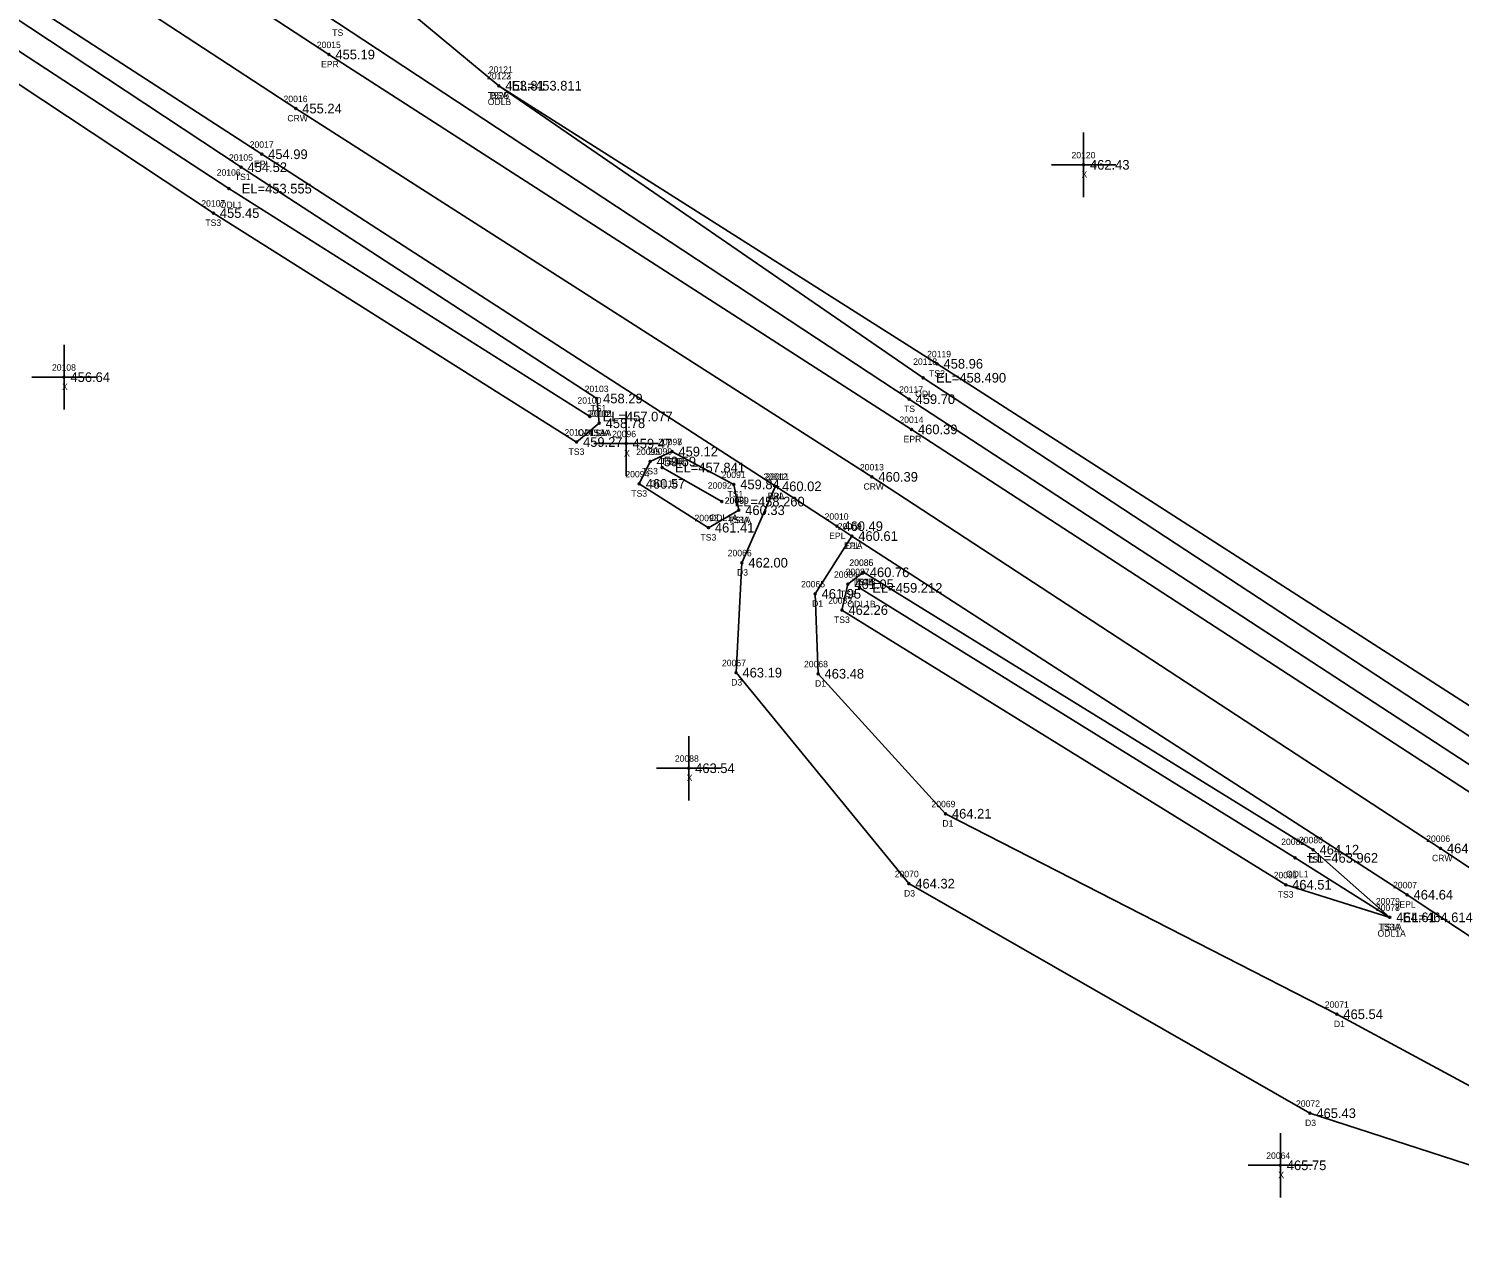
# Model space of a CAD drawing. Extents: x 1797709 to 1799052, y 896018 to 896955.
# Drawn here: x 1798706.7 to 1798928.8, y 896063.3 to 896253.9 of the extents above; entities that cross this region are included whole.
import ezdxf

# ---------------------------------------------------------------- set-up
doc = ezdxf.new("R2010")
doc.units = 0
for name, color, linetype in [('RD_DTM_BkLn1', 7, 'Continuous'), ('RD_DTM_BkLn2', 7, 'Continuous'), ('RD_DTM_BkLn_txCode', 7, 'Continuous'), ('RD_EX_Driveway', 7, 'Continuous'), ('RD_EX_Driveway_txCode', 7, 'Continuous'), ('RD_EX_H2O', 7, 'Continuous'), ('RD_EX_H2O_txCode', 7, 'Continuous'), ('RD_EX_Misc', 7, 'Continuous'), ('RD_EX_Misc_txCode', 7, 'Continuous'), ('RD_EX_Road', 7, 'Continuous'), ('RD_EX_Road_txCode', 7, 'Continuous'), ('RD_EX_TX_Driveway_ELEV', 7, 'Continuous'), ('RD_EX_TX_H2O_ELEV', 7, 'Continuous'), ('RD_EX_TX_Misc_ELEV', 7, 'Continuous'), ('RD_EX_TX_Road_ELEV', 7, 'Continuous'), ('RD_HC_Survey_ELEV', 7, 'Continuous'), ('RD_HC_Survey_txCode', 7, 'Continuous'), ('RD_SMD_Locator', 7, 'Continuous')]:
    doc.layers.add(name, color=color, linetype=linetype)

msp = doc.modelspace()

# ---------------------------------------------------------------- linework, layer by layer
at = {"layer": 'RD_DTM_BkLn1'}
msp.add_lwpolyline([(1799011.08, 896069.91), (1798925.85, 896126.62), (1798837.59, 896184.3), (1798748.15, 896241.48), (1798659.28, 896299.6), (1798569.04, 896359.56), (1798481.49, 896418.06), (1798400.67, 896472.53)], dxfattribs=at)
at = {"layer": 'RD_DTM_BkLn2'}
for points in [[(1798779.67, 896245.03), (1798759.32, 896261.95), (1798678.07, 896324.5), (1798585.68, 896384.49), (1798503.1, 896447.71), (1798419.26, 896491.43), (1798406.44, 896491.18)], [(1799018.13, 896081.6), (1798933.54, 896137.5), (1798843.36, 896196.36), (1798754.6, 896254.77), (1798666.48, 896312.08), (1798576.97, 896371.21), (1798490.12, 896433.01), (1798431.99, 896471.79), (1798411.1, 896485.73), (1798407.22, 896483.62)], [(1798795.25, 896192.62), (1798794.86, 896196.46), (1798739.65, 896232.38), (1798653.27, 896289.5), (1798566.8, 896345.56), (1798563.4, 896344.77), (1798562.95, 896341.35)], [(1798795.25, 896192.62), (1798791.74, 896189.71), (1798735.36, 896225.26), (1798648.32, 896282.88), (1798562.95, 896341.35)], [(1799021.99, 896087.02), (1798938.13, 896143.77), (1798847.7, 896201.86), (1798779.67, 896245.03)], [(1798816.92, 896179.12), (1798812.21, 896176.41), (1798801.47, 896183.22), (1798803.15, 896186.69), (1798806.55, 896188.22)], [(1798816.92, 896179.12), (1798816.14, 896183.12), (1798806.55, 896188.22)], [(1798917.98, 896115.91), (1798901.82, 896120.97), (1798832.94, 896163.62), (1798833.85, 896167.63), (1798836.26, 896169.48)], [(1798917.98, 896115.91), (1798906.08, 896126.41), (1798836.26, 896169.48)]]:
    msp.add_lwpolyline(points, dxfattribs=at)
at = {"layer": 'RD_EX_Driveway'}
for points in [[(1798822.63, 896182.83), (1798817.4, 896170.97), (1798816.49, 896153.9), (1798843.32, 896121.14), (1798905.58, 896085.5), (1798941.17, 896073.98), (1798987.67, 896075.09)], [(1798834.47, 896175.11), (1798828.77, 896166.14), (1798829.23, 896153.73), (1798849.01, 896132), (1798909.77, 896100.86), (1798942.04, 896083.41), (1798974.89, 896083.47)]]:
    msp.add_lwpolyline(points, dxfattribs=at)
at = {"layer": 'RD_EX_H2O'}
msp.add_line((1798814.27, 896180.46), (1798805.01, 896185.74), dxfattribs=at)
for points in [[(1798793.78, 896193.66), (1798737.76, 896229.05), (1798651.14, 896285.8), (1798565.52, 896342.9)], [(1799020.09, 896084.51), (1798935.38, 896140.73), (1798845.54, 896199.69), (1798779.67, 896245.03)], [(1798917.98, 896115.91), (1798903.28, 896125.14), (1798835.65, 896167.06)]]:
    msp.add_lwpolyline(points, dxfattribs=at)
at = {"layer": 'RD_EX_Misc'}
for p, q in [((1798870.44, 896227.75), (1798870.44, 896237.75)), ((1798865.44, 896232.75), (1798875.44, 896232.75)), ((1798712.17, 896194.78), (1798712.17, 896204.78)), ((1798707.17, 896199.78), (1798717.17, 896199.78)), ((1798799.43, 896184.46), (1798799.43, 896194.46)), ((1798794.43, 896189.46), (1798804.43, 896189.46)), ((1798809.15, 896134.06), (1798809.15, 896144.06)), ((1798804.15, 896139.06), (1798814.15, 896139.06)), ((1798900.99, 896072.41), (1798900.99, 896082.41)), ((1798895.99, 896077.41), (1798905.99, 896077.41))]:
    msp.add_line(p, q, dxfattribs=at)
at = {"layer": 'RD_EX_Road'}
for points in [[(1799016.83, 896078.37), (1798931.94, 896134.3), (1798843.73, 896191.67), (1798753.3, 896249.87), (1798664.51, 896307.9), (1798573.47, 896367.69), (1798486.82, 896425.22), (1798405.79, 896479.79), (1798400.67, 896472.53)], [(1799005.77, 896063.27), (1798987.67, 896075.09), (1798974.89, 896083.47), (1798920.67, 896119.42), (1798834.47, 896175.11), (1798832.16, 896176.64), (1798822.63, 896182.83), (1798742.86, 896234.39), (1798653.4, 896292.37), (1798563.64, 896351.71), (1798476.02, 896410.61), (1798395.49, 896463.92), (1798400.67, 896472.53)]]:
    msp.add_lwpolyline(points, dxfattribs=at)
at = {"layer": 'RD_SMD_Locator'}
for centre in [(1798753.3, 896249.87), (1798779.67, 896245.03), (1798779.67, 896245.03), (1798779.67, 896245.03), (1798748.15, 896241.48), (1798739.65, 896232.38), (1798742.86, 896234.39), (1798870.44, 896232.75), (1798737.76, 896229.05), (1798735.36, 896225.26), (1798847.7, 896201.86), (1798712.17, 896199.78), (1798845.54, 896199.69), (1798794.86, 896196.46), (1798843.36, 896196.36), (1798793.78, 896193.66), (1798795.25, 896192.62), (1798795.25, 896192.62), (1798843.73, 896191.67), (1798791.74, 896189.71), (1798799.43, 896189.46), (1798806.55, 896188.22), (1798806.55, 896188.22), (1798803.15, 896186.69), (1798805.01, 896185.74), (1798837.59, 896184.3), (1798801.47, 896183.22), (1798816.14, 896183.12), (1798822.63, 896182.83), (1798822.63, 896182.83), (1798814.27, 896180.46), (1798816.92, 896179.12), (1798816.92, 896179.12), (1798812.21, 896176.41), (1798832.16, 896176.64), (1798834.47, 896175.11), (1798834.47, 896175.11), (1798817.4, 896170.97), (1798836.26, 896169.48), (1798836.26, 896169.48), (1798828.77, 896166.14), (1798833.85, 896167.63), (1798835.65, 896167.06), (1798832.94, 896163.62), (1798816.49, 896153.9), (1798829.23, 896153.73), (1798809.15, 896139.06), (1798849.01, 896132), (1798906.08, 896126.41), (1798925.85, 896126.62), (1798903.28, 896125.14), (1798843.32, 896121.14), (1798901.82, 896120.97), (1798920.67, 896119.42), (1798917.98, 896115.91), (1798917.98, 896115.91), (1798917.98, 896115.91), (1798909.77, 896100.86), (1798905.58, 896085.5), (1798900.99, 896077.41)]:
    msp.add_circle(centre, 0.15, dxfattribs=at)

# ---------------------------------------------------------------- texts
at = {"layer": 'RD_DTM_BkLn_txCode'}
for s, p in [('TS', (1798753.81, 896252.77)), ('20122', (1798777.84, 896246.03)), ('20123', (1798777.84, 896246.03)), ('TS2B', (1798777.95, 896243.03)), ('BSA', (1798778.4, 896243.03)), ('20105', (1798737.78, 896233.38)), ('TS1', (1798738.69, 896230.38)), ('20107', (1798733.48, 896226.26)), ('TS3', (1798734.11, 896223.26)), ('20119', (1798846.15, 896202.86)), ('TS2', (1798846.46, 896199.86)), ('20103', (1798792.99, 896197.46)), ('20117', (1798841.81, 896197.36)), ('TS1', (1798793.9, 896194.46)), ('TS', (1798842.57, 896194.36)), ('20102', (1798793.38, 896193.62)), ('20101', (1798793.66, 896193.62)), ('20104', (1798789.86, 896190.71)), ('TS3A', (1798793.52, 896190.62)), ('TS1A', (1798793.8, 896190.62)), ('TS3', (1798790.49, 896187.71)), ('20095', (1798800.99, 896187.69)), ('20097', (1798804.39, 896189.22)), ('20098', (1798804.39, 896189.22)), ('TS3B', (1798804.83, 896186.22)), ('TS1B', (1798805.11, 896186.22)), ('20094', (1798799.31, 896184.22)), ('TS3', (1798801.9, 896184.69)), ('20091', (1798814.26, 896184.12)), ('TS3', (1798800.23, 896181.22)), ('TS1', (1798815.17, 896181.12)), ('20090', (1798814.73, 896180.12)), ('20089', (1798814.77, 896180.12)), ('20093', (1798810.05, 896177.41)), ('TS3A', (1798815.19, 896177.12)), ('TS1A', (1798815.47, 896177.12)), ('TS3', (1798810.97, 896174.41)), ('20086', (1798834.08, 896170.48)), ('20085', (1798834.1, 896170.48)), ('20084', (1798831.69, 896168.63)), ('TS3B', (1798834.54, 896167.48)), ('TS1B', (1798834.83, 896167.48)), ('TS3', (1798832.61, 896165.63)), ('20083', (1798830.79, 896164.62)), ('TS3', (1798831.7, 896161.62)), ('20080', (1798903.88, 896127.41)), ('TS1', (1798905.12, 896124.41)), ('20081', (1798899.95, 896121.97)), ('TS3', (1798900.58, 896118.97)), ('20077', (1798915.82, 896116.91)), ('20078', (1798915.82, 896116.91)), ('TS3A', (1798916.24, 896113.91)), ('TS1A', (1798916.53, 896113.91))]:
    msp.add_text(s, height=1, dxfattribs=at).set_placement(p)
at = {"layer": 'RD_EX_Driveway_txCode'}
for s, p in [('20012', (1798820.76, 896183.83)), ('D3A', (1798821.39, 896180.83)), ('20009', (1798832.27, 896176.11)), ('20066', (1798815.2, 896171.97)), ('D1A', (1798833.51, 896173.11)), ('D3', (1798816.64, 896168.97)), ('20065', (1798826.59, 896167.14)), ('D1', (1798828.3, 896164.14)), ('20067', (1798814.31, 896154.9)), ('20068', (1798827.04, 896154.73)), ('D3', (1798815.74, 896151.9)), ('D1', (1798828.75, 896151.73)), ('20069', (1798846.83, 896133)), ('D1', (1798848.53, 896130)), ('20070', (1798841.13, 896122.14)), ('D3', (1798842.57, 896119.14)), ('20071', (1798907.89, 896101.86)), ('D1', (1798909.3, 896098.86)), ('20072', (1798903.42, 896086.5)), ('D3', (1798904.82, 896083.5))]:
    msp.add_text(s, height=1, dxfattribs=at).set_placement(p)
at = {"layer": 'RD_EX_H2O_txCode'}
for s, p in [('20121', (1798778.12, 896247.03)), ('ODLB', (1798777.95, 896242.03)), ('20106', (1798735.87, 896231.05)), ('ODL1', (1798736.35, 896226.05)), ('20118', (1798843.99, 896201.69)), ('ODL', (1798844.3, 896196.69)), ('20100', (1798791.87, 896195.66)), ('ODL1A', (1798791.88, 896190.66)), ('20099', (1798802.85, 896187.74)), ('ODL1B', (1798803.13, 896182.74)), ('20092', (1798812.11, 896182.46)), ('ODL1A', (1798812.37, 896177.46)), ('20087', (1798833.5, 896169.06)), ('ODL1B', (1798833.77, 896164.06)), ('20082', (1798901.12, 896127.14)), ('ODL1', (1798901.87, 896122.14)), ('20079', (1798915.82, 896117.91)), ('ODL1A', (1798916.08, 896112.91))]:
    msp.add_text(s, height=1, dxfattribs=at).set_placement(p)
at = {"layer": 'RD_EX_Misc_txCode'}
for s, p in [('20120', (1798868.57, 896233.75)), ('X', (1798870.13, 896230.75)), ('20108', (1798710.3, 896200.78)), ('X', (1798711.86, 896197.78)), ('20096', (1798797.25, 896190.46)), ('X', (1798799.11, 896187.46)), ('20088', (1798806.99, 896140.06)), ('X', (1798808.83, 896137.06)), ('20064', (1798898.8, 896078.41)), ('X', (1798900.67, 896075.41))]:
    msp.add_text(s, height=1, dxfattribs=at).set_placement(p)
at = {"layer": 'RD_EX_Road_txCode'}
for s, p in [('20015', (1798751.42, 896250.87)), ('EPR', (1798752.07, 896247.87)), ('20017', (1798740.99, 896235.39)), ('EPL', (1798741.66, 896232.39)), ('20014', (1798841.85, 896192.67)), ('EPR', (1798842.5, 896189.67)), ('20011', (1798821.04, 896183.83)), ('EPL', (1798821.43, 896180.83)), ('20010', (1798830.24, 896177.64)), ('20008', (1798832.27, 896176.11)), ('EPL', (1798830.95, 896174.64)), ('EPL', (1798833.26, 896173.11)), ('20007', (1798918.48, 896120.42)), ('EPL', (1798919.47, 896117.42))]:
    msp.add_text(s, height=1, dxfattribs=at).set_placement(p)
at = {"layer": 'RD_EX_TX_Driveway_ELEV'}
for s, p in [('460.02', (1798823.63, 896182.08)), ('460.61', (1798835.47, 896174.36)), ('462.00', (1798818.4, 896170.22)), ('461.95', (1798829.77, 896165.39)), ('463.19', (1798817.49, 896153.15)), ('463.48', (1798830.23, 896152.98)), ('464.21', (1798850.01, 896131.25)), ('464.32', (1798844.32, 896120.39)), ('465.54', (1798910.77, 896100.11)), ('465.43', (1798906.58, 896084.75))]:
    msp.add_text(s, height=1.5, dxfattribs=at).set_placement(p)
at = {"layer": 'RD_EX_TX_H2O_ELEV'}
for s, p in [('EL=453.811', (1798781.67, 896244.28)), ('EL=453.555', (1798739.76, 896228.3)), ('EL=458.490', (1798847.54, 896198.94)), ('EL=457.077', (1798795.78, 896192.91)), ('EL=457.841', (1798807.01, 896184.99)), ('EL=458.260', (1798816.27, 896179.71)), ('EL=459.212', (1798837.65, 896166.31)), ('EL=463.962', (1798905.28, 896124.39)), ('EL=464.614', (1798919.98, 896115.16))]:
    msp.add_text(s, height=1.5, dxfattribs=at).set_placement(p)
at = {"layer": 'RD_EX_TX_Misc_ELEV'}
for s, p in [('453.81', (1798780.67, 896244.28)), ('453.81', (1798780.67, 896244.28)), ('454.52', (1798740.65, 896231.63)), ('462.43', (1798871.44, 896232)), ('455.45', (1798736.36, 896224.51)), ('458.96', (1798848.7, 896201.11)), ('456.64', (1798713.17, 896199.03)), ('458.29', (1798795.86, 896195.71)), ('459.70', (1798844.36, 896195.61)), ('458.78', (1798796.25, 896191.87)), ('458.78', (1798796.25, 896191.87)), ('459.27', (1798792.74, 896188.96)), ('459.47', (1798800.43, 896188.71)), ('459.12', (1798807.55, 896187.47)), ('459.12', (1798807.55, 896187.47)), ('459.59', (1798804.15, 896185.94)), ('460.57', (1798802.47, 896182.47)), ('459.84', (1798817.14, 896182.37)), ('460.33', (1798817.92, 896178.37)), ('460.33', (1798817.92, 896178.37)), ('461.41', (1798813.21, 896175.66)), ('460.76', (1798837.26, 896168.73)), ('460.76', (1798837.26, 896168.73)), ('461.05', (1798834.85, 896166.88)), ('462.26', (1798833.94, 896162.87)), ('463.54', (1798810.15, 896138.31)), ('464.12', (1798907.08, 896125.66)), ('464.51', (1798902.82, 896120.22)), ('464.61', (1798918.98, 896115.16)), ('464.61', (1798918.98, 896115.16)), ('465.75', (1798901.99, 896076.66))]:
    msp.add_text(s, height=1.5, dxfattribs=at).set_placement(p)
at = {"layer": 'RD_EX_TX_Road_ELEV'}
for s, p in [('455.19', (1798754.3, 896249.12)), ('454.99', (1798743.86, 896233.64)), ('460.39', (1798844.73, 896190.92)), ('460.02', (1798823.63, 896182.08)), ('460.49', (1798833.16, 896175.89)), ('460.61', (1798835.47, 896174.36)), ('464.64', (1798921.67, 896118.67))]:
    msp.add_text(s, height=1.5, dxfattribs=at).set_placement(p)
at = {"layer": 'RD_HC_Survey_ELEV'}
for s, p in [('455.24', (1798749.15, 896240.73)), ('460.39', (1798838.59, 896183.55)), ('464.66', (1798926.85, 896125.87))]:
    msp.add_text(s, height=1.5, dxfattribs=at).set_placement(p)
at = {"layer": 'RD_HC_Survey_txCode'}
for s, p in [('20016', (1798746.25, 896242.48)), ('CRW', (1798746.84, 896239.48)), ('20013', (1798835.72, 896185.3)), ('CRW', (1798836.28, 896182.3)), ('20006', (1798923.63, 896127.62)), ('CRW', (1798924.53, 896124.62))]:
    msp.add_text(s, height=1, dxfattribs=at).set_placement(p)

doc.saveas('drawing.dxf')
